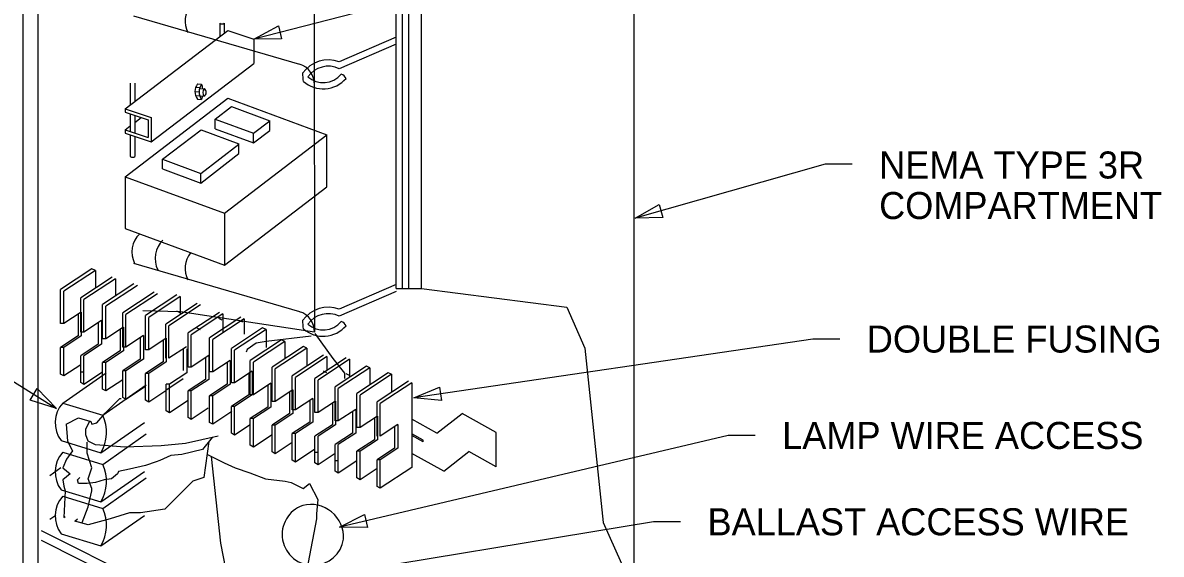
# Model space of a CAD drawing. Extents: x 10314 to 10360.8, y 10093.4 to 10137.8.
# Drawn here: x 10332.56 to 10360.66, y 10109.31 to 10122.42 of the extents above; entities that cross this region are included whole.
import ezdxf

# ---------------------------------------------------------------- set-up
doc = ezdxf.new("R2010")
doc.units = 0
for name, color, linetype in [('G-ANNO-TEXT', 7, 'Continuous'), ('G-DETL-LINE', 7, 'Continuous'), ('G-DETL-OTLN', 7, 'Continuous')]:
    doc.layers.add(name, color=color, linetype=linetype)

msp = doc.modelspace()

# ---------------------------------------------------------------- linework, layer by layer
at = {"layer": 'G-ANNO-TEXT'}
for p, q in [((10348.533, 10124.653), (10338.263, 10122.014)), ((10320.663, 10120.846), (10333.396, 10112.898)), ((10352.365, 10118.928), (10347.673, 10117.593)), ((10353.032, 10118.928), (10352.365, 10118.928)), ((10352.06, 10114.613), (10342.211, 10113.164)), ((10352.727, 10114.613), (10352.06, 10114.613)), ((10349.971, 10112.236), (10340.38, 10109.974)), ((10350.638, 10112.236), (10349.971, 10112.236)), ((10348.129, 10110.106), (10337.729, 10108.395)), ((10348.795, 10110.106), (10348.129, 10110.106))]:
    msp.add_line(p, q, dxfattribs=at)
for points in [[(10338.95, 10122.018), (10338.263, 10122.014), (10338.868, 10122.341)], [(10348.36, 10117.615), (10347.673, 10117.593), (10348.269, 10117.936)], [(10332.918, 10113.392), (10333.396, 10112.898), (10332.742, 10113.109)], [(10342.895, 10113.096), (10342.211, 10113.164), (10342.846, 10113.426)], [(10341.068, 10109.965), (10340.38, 10109.974), (10340.991, 10110.289)]]:
    msp.add_lwpolyline(points, close=True, dxfattribs=at)
at = {"layer": 'G-DETL-LINE'}
for p, q in [((10337.423, 10122.407), (10337.423, 10122.089)), ((10337.533, 10122.407), (10337.533, 10122.173)), ((10335.086, 10120.295), (10337.619, 10122.229)), ((10337.619, 10122.229), (10338.263, 10122.014)), ((10338.263, 10122.014), (10338.263, 10121.412)), ((10335.73, 10119.479), (10338.263, 10121.412)), ((10335.213, 10120.923), (10335.213, 10120.392)), ((10335.324, 10120.923), (10335.324, 10120.477)), ((10336.808, 10120.718), (10336.911, 10120.711)), ((10336.83, 10120.829), (10336.933, 10120.821)), ((10336.871, 10120.906), (10336.975, 10120.899)), ((10337.039, 10120.789), (10336.919, 10120.781)), ((10335.086, 10118.619), (10337.619, 10120.553)), ((10336.83, 10120.619), (10336.933, 10120.612)), ((10336.871, 10120.529), (10336.975, 10120.522)), ((10337.032, 10120.602), (10336.932, 10120.597)), ((10337.619, 10120.553), (10340.068, 10119.648)), ((10335.086, 10120.295), (10335.73, 10120.08)), ((10335.086, 10120.295), (10335.086, 10120.212)), ((10335.086, 10120.212), (10335.651, 10120.024)), ((10335.213, 10120.17), (10335.213, 10119.734)), ((10335.324, 10120.133), (10335.324, 10119.697)), ((10337.308, 10120.041), (10337.708, 10120.347)), ((10337.708, 10120.347), (10338.654, 10119.998)), ((10335.086, 10119.776), (10335.213, 10119.873)), ((10335.324, 10119.958), (10335.483, 10120.08)), ((10335.651, 10120.024), (10335.651, 10119.587)), ((10335.73, 10120.08), (10335.73, 10119.479)), ((10337.308, 10120.041), (10338.253, 10119.692)), ((10337.308, 10119.8), (10337.308, 10120.041)), ((10338.253, 10119.692), (10338.654, 10119.998)), ((10338.654, 10119.757), (10338.654, 10119.998)), ((10335.086, 10119.776), (10335.651, 10119.587)), ((10335.086, 10119.776), (10335.086, 10119.693)), ((10335.086, 10119.693), (10335.73, 10119.479)), ((10335.213, 10119.651), (10335.213, 10119.119)), ((10335.324, 10119.614), (10335.324, 10119.119)), ((10336.01, 10119.05), (10336.959, 10119.775)), ((10336.959, 10119.775), (10337.896, 10119.429)), ((10337.308, 10119.8), (10338.253, 10119.451)), ((10337.535, 10117.715), (10340.068, 10119.648)), ((10338.253, 10119.451), (10338.654, 10119.757)), ((10338.253, 10119.451), (10338.253, 10119.692)), ((10340.068, 10118.368), (10340.068, 10119.648)), ((10336.955, 10118.701), (10337.896, 10119.419)), ((10337.896, 10119.188), (10337.896, 10119.429)), ((10336.01, 10119.05), (10336.955, 10118.701)), ((10336.01, 10118.809), (10336.01, 10119.05)), ((10336.955, 10118.46), (10337.896, 10119.188)), ((10336.01, 10118.809), (10336.955, 10118.46)), ((10335.086, 10118.619), (10337.535, 10117.715)), ((10335.086, 10118.619), (10335.086, 10117.338)), ((10336.955, 10118.46), (10336.955, 10118.701)), ((10337.535, 10116.434), (10340.068, 10118.368)), ((10337.535, 10117.715), (10337.535, 10116.434)), ((10335.086, 10117.338), (10337.535, 10116.434)), ((10334.267, 10116.345), (10333.494, 10115.836)), ((10334.351, 10116.307), (10333.572, 10115.794)), ((10334.351, 10116.307), (10334.267, 10116.345)), ((10334.351, 10116.307), (10334.351, 10115.865)), ((10334.765, 10116.138), (10333.992, 10115.629)), ((10334.848, 10116.099), (10334.07, 10115.586)), ((10335.304, 10115.974), (10334.531, 10115.465)), ((10335.388, 10115.935), (10334.61, 10115.422)), ((10334.848, 10116.099), (10334.848, 10115.674)), ((10333.494, 10114.993), (10333.494, 10115.836)), ((10333.572, 10114.993), (10333.572, 10115.794)), ((10333.992, 10114.785), (10333.992, 10115.629)), ((10335.802, 10115.766), (10335.029, 10115.257)), ((10335.886, 10115.728), (10335.107, 10115.215)), ((10336.363, 10115.701), (10335.59, 10115.191)), ((10336.447, 10115.662), (10335.669, 10115.149)), ((10336.447, 10115.662), (10336.447, 10115.221)), ((10342.401, 10115.857), (10345.985, 10115.404)), ((10334.07, 10114.785), (10334.07, 10115.586)), ((10334.531, 10114.621), (10334.531, 10115.465)), ((10334.61, 10114.621), (10334.61, 10115.422)), ((10336.861, 10115.493), (10336.088, 10114.984)), ((10336.945, 10115.454), (10336.166, 10114.942)), ((10345.985, 10115.404), (10346.436, 10114.387)), ((10334.005, 10115.277), (10333.572, 10114.993)), ((10333.926, 10115.225), (10333.926, 10114.692)), ((10334.005, 10115.277), (10334.005, 10114.692)), ((10334.502, 10115.07), (10334.07, 10114.785)), ((10334.502, 10115.07), (10334.502, 10114.485)), ((10335.029, 10114.414), (10335.029, 10115.257)), ((10335.107, 10114.414), (10335.107, 10115.215)), ((10335.59, 10114.348), (10335.59, 10115.191)), ((10335.669, 10114.348), (10335.669, 10115.149)), ((10336.447, 10115.261), (10336.363, 10115.3)), ((10337.412, 10115.272), (10336.639, 10114.763)), ((10337.495, 10115.233), (10336.717, 10114.721)), ((10337.943, 10115.154), (10337.17, 10114.645)), ((10338.026, 10115.115), (10337.248, 10114.602)), ((10337.484, 10115.078), (10337.4, 10115.117)), ((10337.495, 10115.233), (10337.495, 10114.792)), ((10337.993, 10115.026), (10337.909, 10115.065)), ((10338.026, 10115.115), (10338.026, 10114.735)), ((10333.572, 10114.993), (10333.494, 10114.993)), ((10334.07, 10114.785), (10333.992, 10114.785)), ((10334.424, 10115.018), (10334.424, 10114.485)), ((10335.042, 10114.906), (10334.61, 10114.621)), ((10334.963, 10114.854), (10334.963, 10114.321)), ((10335.042, 10114.906), (10335.042, 10114.321)), ((10336.088, 10114.14), (10336.088, 10114.984)), ((10336.166, 10114.14), (10336.166, 10114.942)), ((10336.945, 10114.841), (10336.861, 10114.88)), ((10338.481, 10114.887), (10337.708, 10114.377)), ((10338.565, 10114.848), (10337.787, 10114.335)), ((10338.565, 10114.848), (10338.481, 10114.887)), ((10338.565, 10114.848), (10338.565, 10114.407)), ((10333.926, 10114.692), (10333.494, 10114.408)), ((10334.005, 10114.692), (10333.572, 10114.408)), ((10334.61, 10114.621), (10334.531, 10114.621)), ((10335.539, 10114.698), (10335.107, 10114.414)), ((10335.461, 10114.646), (10335.461, 10114.113)), ((10335.539, 10114.698), (10335.539, 10114.113)), ((10336.101, 10114.632), (10335.669, 10114.348)), ((10336.022, 10114.581), (10336.022, 10114.048)), ((10336.101, 10114.632), (10336.101, 10114.048)), ((10336.639, 10113.919), (10336.639, 10114.763)), ((10336.717, 10113.919), (10336.717, 10114.721)), ((10337.17, 10113.801), (10337.17, 10114.645)), ((10337.248, 10113.801), (10337.248, 10114.602)), ((10338.945, 10114.59), (10338.172, 10114.081)), ((10339.029, 10114.551), (10338.251, 10114.039)), ((10339.029, 10114.551), (10338.945, 10114.59)), ((10339.029, 10114.551), (10339.029, 10114.126)), ((10333.572, 10114.408), (10333.494, 10114.408)), ((10333.494, 10113.75), (10333.494, 10114.408)), ((10333.572, 10113.704), (10333.572, 10114.408)), ((10334.424, 10114.485), (10333.992, 10114.2)), ((10334.502, 10114.485), (10334.07, 10114.2)), ((10334.963, 10114.321), (10334.531, 10114.036)), ((10335.042, 10114.321), (10334.61, 10114.036)), ((10335.107, 10114.414), (10335.029, 10114.414)), ((10335.669, 10114.348), (10335.59, 10114.348)), ((10336.599, 10114.425), (10336.166, 10114.14)), ((10336.52, 10114.373), (10336.52, 10113.84)), ((10336.61, 10114.368), (10336.61, 10113.783)), ((10337.708, 10113.534), (10337.708, 10114.377)), ((10337.787, 10113.534), (10337.787, 10114.335)), ((10339.485, 10114.426), (10338.712, 10113.917)), ((10339.569, 10114.387), (10338.791, 10113.875)), ((10339.569, 10114.387), (10339.485, 10114.426)), ((10339.569, 10114.387), (10339.569, 10113.946)), ((10346.436, 10114.387), (10346.888, 10110.091)), ((10333.992, 10113.98), (10333.572, 10113.704)), ((10333.992, 10113.542), (10333.992, 10114.2)), ((10334.07, 10113.496), (10334.07, 10114.2)), ((10334.531, 10113.378), (10334.531, 10114.036)), ((10334.61, 10114.036), (10334.531, 10114.036)), ((10334.61, 10113.332), (10334.61, 10114.036)), ((10335.461, 10114.113), (10335.029, 10113.829)), ((10335.539, 10114.113), (10335.107, 10113.829)), ((10336.022, 10114.048), (10335.59, 10113.763)), ((10336.101, 10114.048), (10335.669, 10113.763)), ((10337.149, 10114.204), (10336.717, 10113.919)), ((10337.071, 10114.152), (10337.071, 10113.619)), ((10337.149, 10114.204), (10337.149, 10113.619)), ((10337.68, 10114.085), (10337.248, 10113.801)), ((10337.602, 10114.034), (10337.602, 10113.501)), ((10337.68, 10114.085), (10337.68, 10113.501)), ((10338.172, 10113.237), (10338.172, 10114.081)), ((10338.251, 10113.237), (10338.251, 10114.039)), ((10339.983, 10114.219), (10339.21, 10113.709)), ((10340.067, 10114.18), (10339.288, 10113.667)), ((10340.544, 10114.153), (10339.771, 10113.644)), ((10340.628, 10114.114), (10339.85, 10113.601)), ((10340.067, 10114.18), (10340.067, 10113.838)), ((10341.042, 10113.945), (10340.269, 10113.436)), ((10340.628, 10114.114), (10340.628, 10113.673)), ((10341.126, 10113.907), (10341.042, 10113.945)), ((10333.572, 10113.704), (10333.494, 10113.75)), ((10333.547, 10113.034), (10334.618, 10113.784)), ((10334.07, 10113.799), (10333.992, 10113.799)), ((10334.531, 10113.8), (10334.07, 10113.496)), ((10335.107, 10113.829), (10335.029, 10113.829)), ((10335.029, 10113.171), (10335.029, 10113.829)), ((10335.107, 10113.125), (10335.107, 10113.829)), ((10335.59, 10113.105), (10335.59, 10113.763)), ((10335.669, 10113.763), (10335.59, 10113.763)), ((10335.669, 10113.059), (10335.669, 10113.763)), ((10336.61, 10113.783), (10336.178, 10113.499)), ((10336.717, 10113.919), (10336.639, 10113.919)), ((10337.248, 10113.801), (10337.17, 10113.801)), ((10338.219, 10113.818), (10337.787, 10113.534)), ((10338.14, 10113.767), (10338.14, 10113.234)), ((10338.219, 10113.818), (10338.219, 10113.234)), ((10338.712, 10113.073), (10338.712, 10113.917)), ((10338.791, 10113.073), (10338.791, 10113.875)), ((10339.21, 10112.866), (10339.21, 10113.709)), ((10339.288, 10112.866), (10339.288, 10113.667)), ((10340.067, 10113.779), (10339.983, 10113.818)), ((10341.126, 10113.907), (10340.347, 10113.394)), ((10340.628, 10113.713), (10340.544, 10113.752)), ((10341.581, 10113.781), (10340.808, 10113.272)), ((10341.665, 10113.743), (10340.887, 10113.23)), ((10341.126, 10113.907), (10341.126, 10113.481)), ((10341.665, 10113.743), (10341.581, 10113.781)), ((10341.665, 10113.743), (10341.665, 10113.301)), ((10334.07, 10113.496), (10333.992, 10113.542)), ((10334.61, 10113.332), (10334.531, 10113.378)), ((10334.532, 10112.734), (10335.604, 10113.484)), ((10335.029, 10113.608), (10334.61, 10113.332)), ((10335.59, 10113.443), (10335.107, 10113.125)), ((10336.52, 10113.628), (10336.088, 10113.343)), ((10336.178, 10113.499), (10336.099, 10113.499)), ((10336.099, 10112.841), (10336.099, 10113.499)), ((10336.178, 10112.795), (10336.178, 10113.499)), ((10337.071, 10113.619), (10336.639, 10113.335)), ((10337.149, 10113.619), (10336.717, 10113.335)), ((10337.602, 10113.501), (10337.17, 10113.216)), ((10337.68, 10113.501), (10337.248, 10113.216)), ((10337.787, 10113.534), (10337.708, 10113.534)), ((10338.683, 10113.522), (10338.251, 10113.237)), ((10338.605, 10113.47), (10338.605, 10112.937)), ((10338.683, 10113.522), (10338.683, 10112.937)), ((10339.771, 10112.8), (10339.771, 10113.644)), ((10339.85, 10112.8), (10339.85, 10113.601)), ((10340.269, 10112.593), (10340.269, 10113.436)), ((10340.347, 10112.593), (10340.347, 10113.394)), ((10342.079, 10113.574), (10341.306, 10113.065)), ((10342.163, 10113.535), (10341.384, 10113.022)), ((10342.163, 10113.535), (10342.163, 10111.445)), ((10335.107, 10113.125), (10335.029, 10113.171)), ((10335.669, 10113.059), (10335.59, 10113.105)), ((10336.088, 10113.335), (10335.669, 10113.059)), ((10336.639, 10113.098), (10336.178, 10112.795)), ((10336.717, 10113.335), (10336.639, 10113.335)), ((10336.639, 10112.677), (10336.639, 10113.335)), ((10336.717, 10112.631), (10336.717, 10113.335)), ((10337.17, 10112.558), (10337.17, 10113.216)), ((10337.248, 10113.216), (10337.17, 10113.216)), ((10337.248, 10112.512), (10337.248, 10113.216)), ((10338.14, 10113.234), (10337.708, 10112.949)), ((10338.219, 10113.234), (10337.787, 10112.949)), ((10338.251, 10113.237), (10338.172, 10113.237)), ((10339.223, 10113.358), (10338.791, 10113.073)), ((10339.144, 10113.306), (10339.144, 10112.773)), ((10339.223, 10113.358), (10339.223, 10112.773)), ((10339.72, 10113.15), (10339.288, 10112.866)), ((10339.642, 10113.099), (10339.642, 10112.566)), ((10339.72, 10113.15), (10339.72, 10112.566)), ((10340.808, 10112.429), (10340.808, 10113.272)), ((10340.887, 10112.429), (10340.887, 10113.23)), ((10333.547, 10113.034), (10334.532, 10112.734)), ((10336.178, 10112.795), (10336.099, 10112.841)), ((10337.136, 10112.907), (10336.717, 10112.631)), ((10337.719, 10112.823), (10337.248, 10112.512)), ((10337.708, 10112.291), (10337.708, 10112.949)), ((10337.787, 10112.949), (10337.708, 10112.949)), ((10337.787, 10112.245), (10337.787, 10112.949)), ((10338.605, 10112.937), (10338.172, 10112.653)), ((10338.683, 10112.937), (10338.251, 10112.653)), ((10338.791, 10113.073), (10338.712, 10113.073)), ((10339.288, 10112.866), (10339.21, 10112.866)), ((10340.282, 10113.085), (10339.85, 10112.8)), ((10340.203, 10113.033), (10340.203, 10112.5)), ((10340.282, 10113.085), (10340.282, 10112.5)), ((10340.779, 10112.877), (10340.347, 10112.593)), ((10340.701, 10112.825), (10340.701, 10112.292)), ((10340.779, 10112.877), (10340.779, 10112.292)), ((10341.306, 10112.221), (10341.306, 10113.065)), ((10341.384, 10112.221), (10341.384, 10113.022)), ((10334.49, 10111.807), (10335.561, 10112.557)), ((10336.717, 10112.631), (10336.639, 10112.677)), ((10337.248, 10112.512), (10337.17, 10112.558)), ((10338.251, 10112.653), (10338.172, 10112.653)), ((10338.172, 10111.995), (10338.172, 10112.653)), ((10338.251, 10111.949), (10338.251, 10112.653)), ((10339.144, 10112.773), (10338.712, 10112.488)), ((10339.223, 10112.773), (10338.791, 10112.488)), ((10339.642, 10112.566), (10339.21, 10112.281)), ((10339.72, 10112.566), (10339.288, 10112.281)), ((10339.85, 10112.8), (10339.771, 10112.8)), ((10340.347, 10112.593), (10340.269, 10112.593)), ((10341.319, 10112.713), (10340.887, 10112.429)), ((10341.24, 10112.661), (10341.24, 10112.128)), ((10341.319, 10112.713), (10341.319, 10112.128)), ((10342.781, 10112.294), (10342.163, 10112.635)), ((10342.781, 10112.294), (10343.406, 10112.778)), ((10344.248, 10112.312), (10343.406, 10112.778)), ((10334.532, 10111.521), (10335.604, 10112.271)), ((10337.787, 10112.245), (10337.708, 10112.291)), ((10338.172, 10112.499), (10337.787, 10112.245)), ((10338.712, 10112.252), (10338.251, 10111.949)), ((10338.791, 10112.488), (10338.712, 10112.488)), ((10338.712, 10111.831), (10338.712, 10112.488)), ((10338.791, 10111.785), (10338.791, 10112.488)), ((10339.21, 10111.623), (10339.21, 10112.281)), ((10339.288, 10112.281), (10339.21, 10112.281)), ((10339.288, 10111.577), (10339.288, 10112.281)), ((10340.203, 10112.5), (10339.771, 10112.215)), ((10340.282, 10112.5), (10339.85, 10112.215)), ((10340.701, 10112.292), (10340.269, 10112.008)), ((10340.779, 10112.292), (10340.347, 10112.008)), ((10340.887, 10112.429), (10340.808, 10112.429)), ((10341.817, 10112.506), (10341.384, 10112.221)), ((10341.738, 10112.454), (10341.738, 10111.921)), ((10341.817, 10112.506), (10341.817, 10111.921)), ((10342.445, 10112.122), (10342.163, 10112.278)), ((10344.248, 10111.464), (10344.248, 10112.312)), ((10333.504, 10112.107), (10334.49, 10111.807)), ((10338.251, 10111.949), (10338.172, 10111.995)), ((10339.21, 10112.061), (10338.791, 10111.785)), ((10339.771, 10111.557), (10339.771, 10112.215)), ((10339.85, 10111.511), (10339.85, 10112.215)), ((10340.269, 10111.35), (10340.269, 10112.008)), ((10340.347, 10111.304), (10340.347, 10112.008)), ((10341.24, 10112.128), (10340.808, 10111.844)), ((10341.319, 10112.128), (10340.887, 10111.844)), ((10342.445, 10112.079), (10342.163, 10112.235)), ((10342.445, 10112.079), (10342.445, 10112.122)), ((10333.547, 10111.821), (10334.532, 10111.521)), ((10338.791, 10111.785), (10338.712, 10111.831)), ((10339.771, 10111.895), (10339.288, 10111.577)), ((10339.85, 10111.814), (10339.771, 10111.814)), ((10340.269, 10111.787), (10339.85, 10111.511)), ((10340.808, 10111.186), (10340.808, 10111.844)), ((10340.887, 10111.844), (10340.808, 10111.844)), ((10340.887, 10111.14), (10340.887, 10111.844)), ((10341.738, 10111.921), (10341.306, 10111.636)), ((10341.817, 10111.921), (10341.384, 10111.636)), ((10342.949, 10111.353), (10342.163, 10111.787)), ((10342.949, 10111.353), (10343.573, 10111.837)), ((10344.248, 10111.464), (10343.573, 10111.837)), ((10339.288, 10111.577), (10339.21, 10111.623)), ((10339.85, 10111.511), (10339.771, 10111.557)), ((10340.347, 10111.607), (10340.269, 10111.607)), ((10340.808, 10111.608), (10340.347, 10111.304)), ((10341.306, 10111.416), (10340.887, 10111.14)), ((10341.384, 10111.636), (10341.306, 10111.636)), ((10341.306, 10110.978), (10341.306, 10111.636)), ((10341.384, 10110.932), (10341.384, 10111.636)), ((10342.163, 10111.445), (10341.384, 10110.932)), ((10334.49, 10110.595), (10335.561, 10111.345)), ((10334.532, 10110.436), (10335.604, 10111.186)), ((10340.347, 10111.304), (10340.269, 10111.35)), ((10340.887, 10111.14), (10340.808, 10111.186)), ((10333.504, 10110.895), (10334.49, 10110.595)), ((10341.384, 10110.932), (10341.306, 10110.978)), ((10333.547, 10110.736), (10334.532, 10110.436)), ((10334.49, 10109.51), (10335.561, 10110.26)), ((10346.888, 10110.091), (10347.34, 10109.073)), ((10333.504, 10109.81), (10334.49, 10109.51))]:
    msp.add_line(p, q, dxfattribs=at)
for centre, radius, start, end in [((10337.478, 10122.469), 0.0831, 228.34, 311.66), ((10337.118, 10120.718), 0.31, 142.601, 217.3991), ((10337.221, 10120.711), 0.31, 142.601, 217.3991), ((10336.478, 10120.711), 0.532, 8.2302, 20.76), ((10337.175, 10120.69), 0.168, 143.9445, 211.5376), ((10336.981, 10120.698), 0.108, 298.1123, 57.3698), ((10336.478, 10120.711), 0.532, 339.24, 348.035), ((10335.269, 10119.181), 0.0831, 228.34, 311.66), ((10334.087, 10112.544), 0.729, 137.8451, 216.8579), ((10333.627, 10112.311), 0.999, 329.6995, 25.0036), ((10334.087, 10111.332), 0.729, 137.8451, 216.8579), ((10333.627, 10111.099), 0.999, 329.6995, 25.0036), ((10334.087, 10110.247), 0.729, 137.8451, 216.8579), ((10333.627, 10110.014), 0.999, 329.6995, 25.0036), ((10339.724, 10109.791), 0.762, 109.4878, 351.4682), ((10339.667, 10109.722), 0.811, 356.9033, 104.0527)]:
    msp.add_arc(centre, radius, start, end, dxfattribs=at)
at = {"layer": 'G-DETL-OTLN'}
for p, q in [((10347.649, 10105.044), (10347.649, 10133.422)), ((10332.562, 10132.634), (10332.562, 10105.735)), ((10332.933, 10132.418), (10332.933, 10106.019)), ((10341.773, 10115.857), (10341.773, 10128.866)), ((10341.93, 10115.857), (10341.93, 10128.988)), ((10342.087, 10115.857), (10342.087, 10127.503)), ((10342.401, 10115.857), (10342.401, 10127.559)), ((10339.75, 10126.849), (10339.757, 10114.781)), ((10341.773, 10122.061), (10340.37, 10121.453)), ((10341.773, 10121.889), (10340.371, 10121.282)), ((10341.773, 10115.957), (10340.37, 10115.35)), ((10341.773, 10115.786), (10340.371, 10115.179)), ((10341.773, 10115.857), (10342.401, 10115.857)), ((10333.23, 10111.251), (10333.502, 10111.441)), ((10333.23, 10110.166), (10333.375, 10110.267)), ((10333.012, 10109.891), (10341.879, 10105.455)), ((10333.012, 10109.651), (10341.879, 10105.215))]:
    msp.add_line(p, q, dxfattribs=at)
msp.add_lwpolyline([(10332.562, 10132.634), (10332.562, 10105.735), (10332.318, 10105.87), (10332.324, 10132.724)], close=True, dxfattribs=at)
for points in [[(10335.292, 10122.586), (10339.393, 10121.392)], [(10335.292, 10116.483), (10339.393, 10115.289)], [(10339.757, 10114.781), (10336.454, 10115.288), (10335.52, 10115.31)], [(10339.678, 10114.687), (10338.566, 10114.553), (10338.322, 10114.509), (10338.099, 10114.353), (10338.077, 10114.286)], [(10339.767, 10114.754), (10340.212, 10114.13), (10340.501, 10113.774), (10340.501, 10113.641)], [(10333.632, 10112.515), (10333.937, 10112.667), (10334.236, 10112.577), (10334.266, 10112.517), (10334.386, 10112.547), (10334.596, 10112.787), (10334.956, 10113.147), (10334.986, 10113.147)], [(10337.384, 10112.217), (10336.575, 10112.037), (10335.975, 10111.977), (10335.076, 10111.947), (10334.356, 10112.007), (10334.177, 10112.097), (10334.117, 10112.247), (10334.117, 10112.397), (10334.221, 10112.607)], [(10333.632, 10112.515), (10333.667, 10112.097), (10333.787, 10111.857), (10333.637, 10111.647), (10333.547, 10111.437), (10333.727, 10111.287), (10333.547, 10111.137), (10333.577, 10110.987), (10333.607, 10110.867), (10333.577, 10110.208), (10333.607, 10110.238)], [(10337.151, 10112.083), (10337.025, 10111.197), (10336.755, 10111.107), (10336.065, 10110.418), (10335.466, 10110.328), (10335.196, 10110.328), (10334.716, 10110.178), (10334.177, 10110.028), (10333.847, 10110.118), (10333.907, 10110.178)], [(10337.234, 10112.187), (10336.995, 10111.887), (10336.485, 10111.767), (10336.215, 10111.737), (10335.945, 10111.617), (10335.855, 10111.587), (10335.586, 10111.497), (10335.196, 10111.407), (10334.926, 10111.347), (10334.896, 10111.287), (10334.746, 10111.167), (10334.566, 10111.137), (10334.356, 10111.077), (10334.147, 10111.047), (10333.937, 10111.047), (10333.907, 10111.137), (10333.967, 10111.197)], [(10334.027, 10110.088), (10334.177, 10110.478), (10334.266, 10110.867), (10334.266, 10110.927), (10334.177, 10111.167), (10334.266, 10111.437), (10334.147, 10111.797), (10334.147, 10112.067)], [(10337.106, 10111.771), (10337.534, 10111.557), (10337.804, 10111.437), (10338.164, 10111.317), (10338.553, 10111.167), (10339.033, 10111.107), (10339.183, 10111.077), (10339.483, 10110.927), (10339.633, 10111.047), (10339.843, 10110.657), (10339.813, 10110.298), (10339.813, 10110.178), (10339.603, 10109.098), (10339.603, 10109.039)], [(10337.21, 10111.719), (10337.444, 10109.578), (10337.624, 10108.648), (10337.684, 10108.108), (10337.684, 10107.748), (10337.683, 10107.746)]]:
    msp.add_lwpolyline(points, dxfattribs=at)
for centre, radius, start, end in [((10337.187, 10122.46), 0.619, 141.598, 207.2158), ((10339.251, 10120.905), 0.507, 357.5847, 73.7678), ((10340.101, 10120.723), 0.778, 69.7124, 144.4339), ((10340.101, 10120.723), 0.621, 64.1717, 144.7376), ((10340.206, 10121.131), 0.74, 176.5465, 192.7165), ((10339.975, 10121.529), 0.744, 228.8503, 319.2199), ((10339.975, 10121.529), 0.587, 229.5848, 319.2199), ((10340.357, 10120.953), 0.202, 26.3148, 72.125), ((10335.872, 10116.762), 0.619, 133.4556, 207.2158), ((10336.445, 10116.604), 0.619, 133.4556, 207.2158), ((10337.187, 10116.357), 0.619, 141.598, 207.2158), ((10340.101, 10114.62), 0.778, 69.7124, 144.4339), ((10339.251, 10114.802), 0.507, 357.5847, 73.7678), ((10340.206, 10115.028), 0.74, 176.5465, 192.7165), ((10340.101, 10114.62), 0.621, 64.1717, 144.7376), ((10339.975, 10115.426), 0.744, 228.8503, 319.2199), ((10339.975, 10115.426), 0.587, 229.5848, 319.2199), ((10340.357, 10114.85), 0.202, 26.3148, 72.125)]:
    msp.add_arc(centre, radius, start, end, dxfattribs=at)

# ---------------------------------------------------------------- texts
at = {"layer": 'G-ANNO-TEXT'}
for s, p in [('NEMA TYPE 3R', (10353.698, 10118.574)), ('COMPARTMENT', (10353.698, 10117.574)), ('DOUBLE FUSING', (10353.394, 10114.28)), ('LAMP WIRE ACCESS', (10351.305, 10111.903)), ('BALLAST ACCESS WIRE', (10349.462, 10109.772))]:
    msp.add_text(s, height=0.66667, dxfattribs=at).set_placement(p)

doc.saveas('drawing.dxf')
